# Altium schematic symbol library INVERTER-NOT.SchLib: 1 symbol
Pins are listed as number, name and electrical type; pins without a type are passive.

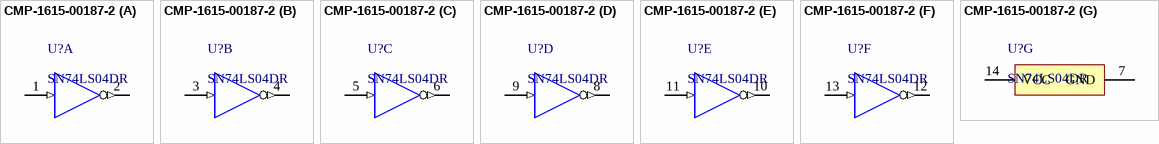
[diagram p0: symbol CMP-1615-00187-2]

## CMP-1615-00187-2
designator U?, comment SN74LS04DR
Hex inverters, D0014A, LARGE T&R; Manufacturer: Texas Instruments; Output Drive (IOL/IOH)(Max)(mA): -0.4/8; F @ Nom Voltage(Max)(Mhz): 35; Rating: Catalog; Voltage(Nom)(V): 5; Input Type: TTL; Bits(#): 6; tpd @ Nom Voltage(Max)(ns): 22; Schmitt Trigger: No; ICC @ Nom Voltage(Max)(mA): 0.033; Technology Family: LS; VCC(Min)(V): 4.75; Output Type: CMOS; VCC(Max)(V): 5.25
footprint D0014A_L (SOIC, 14-Leads, Body 8.75x4mm, Pitch 1.27mm, IPC High Density)
footprint D0014A_N (SOIC, 14-Leads, Body 8.75x4mm, Pitch 1.27mm, IPC Medium Density)
footprint D0014A_M (SOIC, 14-Leads, Body 8.75x4mm, Pitch 1.27mm, IPC Low Density)
part A pins: 1 1A (in) "Input 1A", 2 ~{1Y} (out) "Output 1Y"
part B pins: 3 2A (in) "Input 2A", 4 ~{2Y} (out) "Output 2Y"
part C pins: 5 3A (in) "Input 3A", 6 ~{3Y} (out) "Output 3Y"
part D pins: 8 ~{4Y} (out) "Output 4Y", 9 4A (in) "Input 4A"
part E pins: 10 ~{5Y} (out) "Output 5Y", 11 5A (in) "Input 5A"
part F pins: 12 ~{6Y} (out) "Output 6Y", 13 6A (in) "Input 6A"
part G pins: 7 GND (power) "Ground Pin", 14 VCC (power) "Power Pin"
